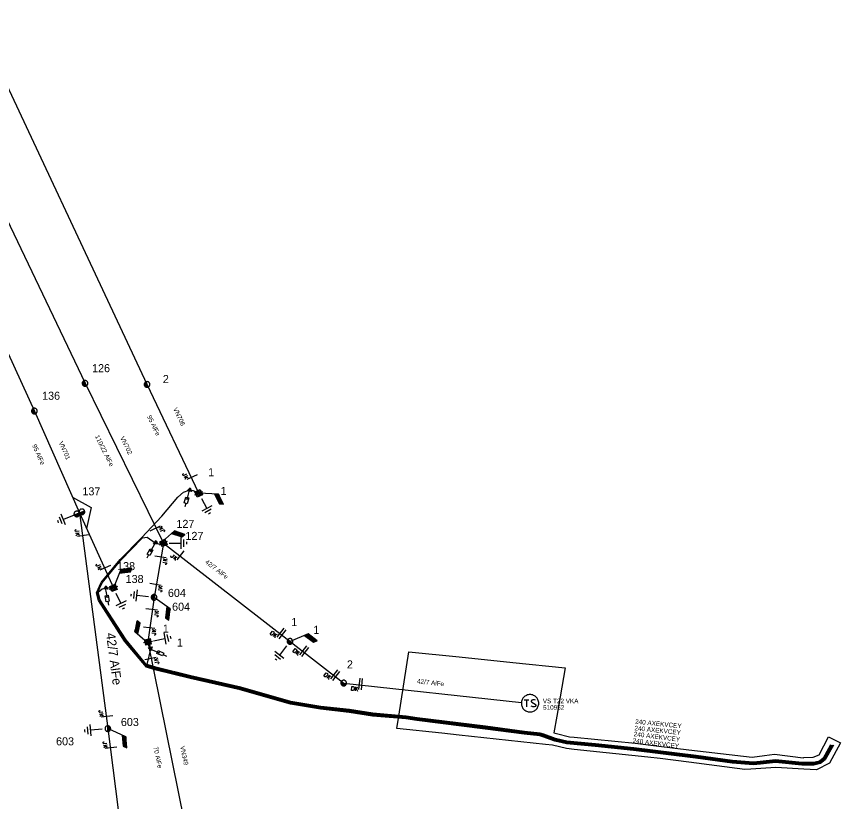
# Model space of a CAD drawing. Extents: x -536397 to -535454, y -1201642 to -1200953.
# Drawn here: x -536258.8 to -536079.5, y -1201331.1 to -1201160.3 of the extents above; entities that cross this region are included whole.
import ezdxf

# ---------------------------------------------------------------- set-up
doc = ezdxf.new("R2010")
doc.units = 0
for name, color, linetype in [('Default', 7, 'Continuous'), ('Vrstva 1', 7, 'Continuous'), ('Vrstva 11', 7, 'Continuous'), ('Vrstva 12', 7, 'Continuous'), ('Vrstva 13', 7, 'Continuous'), ('Vrstva 14', 7, 'Continuous'), ('Vrstva 15', 7, 'Continuous'), ('Vrstva 16', 7, 'Continuous'), ('Vrstva 18', 7, 'Continuous'), ('Vrstva 19', 7, 'Continuous'), ('Vrstva 2', 7, 'Continuous'), ('Vrstva 25', 7, 'Continuous'), ('Vrstva 26', 7, 'Continuous'), ('Vrstva 27', 7, 'Continuous'), ('Vrstva 3', 7, 'Continuous'), ('Vrstva 35', 7, 'Continuous'), ('Vrstva 4', 7, 'Continuous'), ('Vrstva 5', 7, 'Continuous'), ('Vrstva 52', 7, 'Continuous'), ('Vrstva 53', 7, 'Continuous'), ('Vrstva 57', 7, 'Continuous'), ('Vrstva 6', 7, 'Continuous')]:
    doc.layers.add(name, color=color, linetype=linetype)

# ---------------------------------------------------------------- blocks, each defined once
blk = doc.blocks.new('VN850')
at = {"layer": 'Vrstva 15'}
for points in [[(-0.56, 1.43), (-0.56, -1.07)], [(-0.01, 1.43), (-0.01, -1.07)], [(-2.09, -0.54), (-1.78, -0.54)], [(-2.09, -1.41), (-2.09, -0.54)], [(-1.78, -1.41), (-2.09, -1.41)], [(-1.78, -0.54), (-1.66, -0.6)], [(-1.67, -1.35), (-1.78, -1.41)], [(-1.59, -1.2), (-1.67, -1.35)], [(-1.66, -0.6), (-1.59, -0.75)], [(-1.59, -0.75), (-1.55, -0.96)], [(-1.55, -0.96), (-1.59, -1.2)], [(-1.26, -0.54), (-1.26, -1.41)], [(-0.85, -0.54), (-1.26, -1.09)], [(-1.13, -0.92), (-0.77, -1.41)]]:
    blk.add_lwpolyline(points, dxfattribs=at)
blk = doc.blocks.new('VN840')
at = {"layer": 'Vrstva 15'}
for points in [[(-0.01, 1.41), (-0.01, -1.09)], [(-1.51, -1.24), (-1.51, -1.15)], [(-1.48, -1.35), (-1.51, -1.24)], [(-1.33, -1.42), (-1.48, -1.35)], [(-1.27, -1.42), (-1.33, -1.42)], [(-1.13, -1.35), (-1.27, -1.42)], [(-1.09, -1.24), (-1.13, -1.35)], [(-1.09, -0.59), (-1.09, -1.24)], [(-0.68, -0.59), (-0.68, -1.42)], [(-0.68, -1.11), (-0.27, -0.59)], [(-0.54, -0.94), (-0.2, -1.42)]]:
    blk.add_lwpolyline(points, dxfattribs=at)
blk = doc.blocks.new('VN860')
at = {"layer": 'Vrstva 15'}
for points in [[(-3.74, 0), (0.01, 2.82)], [(0.01, 2.82), (3.76, 0)]]:
    blk.add_lwpolyline(points, dxfattribs=at)
blk = doc.blocks.new('VN440')
at = {"layer": 'Vrstva 2'}
for points in [[(1.22, 0), (1.21, 0.13), (1.19, 0.25), (1.16, 0.38), (1.11, 0.5), (1.05, 0.61), (0.98, 0.72), (0.9, 0.82), (0.81, 0.91), (0.71, 0.99), (0.6, 1.06), (0.49, 1.12), (0.37, 1.16), (0.25, 1.2), (0.12, 1.22), (-0.01, 1.22), (-0.14, 1.22), (-0.26, 1.2), (-0.39, 1.16), (-0.51, 1.12), (-0.62, 1.06), (-0.73, 0.99), (-0.83, 0.91), (-0.92, 0.82), (-1, 0.72), (-1.07, 0.61), (-1.13, 0.5), (-1.18, 0.38), (-1.21, 0.25), (-1.23, 0.13), (-1.24, 0), (-1.23, -0.13), (-1.21, -0.26), (-1.18, -0.38), (-1.13, -0.5), (-1.07, -0.62), (-1, -0.73), (-0.92, -0.83), (-0.83, -0.92), (-0.73, -1), (-0.62, -1.07), (-0.51, -1.13), (-0.39, -1.17), (-0.26, -1.2), (-0.14, -1.23), (-0.01, -1.23), (0.12, -1.23), (0.25, -1.2), (0.37, -1.17), (0.49, -1.13), (0.6, -1.07), (0.71, -1), (0.81, -0.92), (0.9, -0.83), (0.98, -0.73), (1.05, -0.62), (1.11, -0.5), (1.16, -0.38), (1.19, -0.26), (1.21, -0.13), (1.22, 0)], [(-1.24, 0), (1.22, 0)], [(-1.18, -0.34), (1.1, -0.34)], [(-1.01, -0.63), (0.97, -0.63)], [(-0.74, -0.92), (0.68, -0.92)]]:
    blk.add_lwpolyline(points, dxfattribs=at)
blk = doc.blocks.new('VN890')
at = {"layer": 'Vrstva 4'}
for points in [[(-0.41, 0.41), (0.41, 0)], [(-0.41, -0.41), (-0.41, 0.41)], [(0.41, 0), (-0.41, -0.41)], [(-0.34, 0.31), (0.27, 0), (-0.34, -0.3), (-0.34, 0.31)], [(-0.26, 0.2), (0.1, 0), (-0.26, -0.18), (-0.26, 0.2)], [(-0.19, 0.09), (-0.04, 0), (-0.19, -0.08), (-0.19, 0.09)], [(-0.16, -0.01), (-0.16, 0.03), (-0.13, 0.01), (-0.16, -0.01)]]:
    blk.add_lwpolyline(points, dxfattribs=at)
blk = doc.blocks.new('VN820')
at = {"layer": 'Vrstva 13'}
for points in [[(0, 0), (0, -2.1)], [(-0.32, -1.63), (0.34, -1.63)], [(-0.32, -2.95), (-0.32, -1.63)], [(0.34, -1.63), (0.34, -2.95)], [(0.34, -2.95), (-0.32, -2.95)], [(0, -2.1), (-0.12, -1.86)], [(0, -2.1), (0.12, -1.86)], [(0, -2.95), (0, -3.75)]]:
    blk.add_lwpolyline(points, dxfattribs=at)
blk = doc.blocks.new('VN810')
at = {"layer": 'Vrstva 14'}
for points in [[(0, -1.25), (0, -3.75)], [(1.25, -3.75), (-1.25, -3.75)], [(0.77, -4.37), (-0.8, -4.37)], [(0, -5), (-0.25, -5)], [(0.27, -5), (0, -5)]]:
    blk.add_lwpolyline(points, dxfattribs=at)
blk = doc.blocks.new('VN610')
at = {"layer": 'Vrstva 6'}
for points in [[(1.88, 0), (1.87, 0.2), (1.84, 0.39), (1.79, 0.58), (1.72, 0.77), (1.63, 0.94), (1.52, 1.11), (1.4, 1.26), (1.26, 1.4), (1.1, 1.53), (0.94, 1.63), (0.76, 1.72), (0.58, 1.8), (0.39, 1.85), (0.19, 1.88), (-0.01, 1.89), (-0.21, 1.88), (-0.4, 1.85), (-0.59, 1.8), (-0.78, 1.72), (-0.95, 1.63), (-1.12, 1.53), (-1.27, 1.4), (-1.41, 1.26), (-1.54, 1.11), (-1.64, 0.94), (-1.73, 0.77), (-1.8, 0.58), (-1.86, 0.39), (-1.89, 0.2), (-1.9, 0), (-1.89, -0.2), (-1.86, -0.39), (-1.8, -0.58), (-1.73, -0.77), (-1.64, -0.95), (-1.54, -1.11), (-1.41, -1.27), (-1.27, -1.41), (-1.12, -1.53), (-0.95, -1.64), (-0.78, -1.73), (-0.59, -1.8), (-0.4, -1.85), (-0.21, -1.88), (-0.01, -1.89), (0.19, -1.88), (0.39, -1.85), (0.58, -1.8), (0.76, -1.73), (0.94, -1.64), (1.1, -1.53), (1.26, -1.41), (1.4, -1.27), (1.52, -1.11), (1.63, -0.95), (1.72, -0.77), (1.79, -0.58), (1.84, -0.39), (1.87, -0.2), (1.88, 0)], [(-1.27, 0.78), (-0.26, 0.78)], [(-0.76, 0.78), (-0.76, -0.79)], [(1.19, 0.66), (0.94, 0.78), (0.62, 0.78), (0.37, 0.66), (0.24, 0.47), (0.24, 0.4), (0.37, 0.22), (1.12, -0.16), (1.25, -0.32), (1.25, -0.48), (1.12, -0.67), (0.87, -0.79), (0.62, -0.79), (0.49, -0.73), (0.24, -0.6)]]:
    blk.add_lwpolyline(points, dxfattribs=at)
blk = doc.blocks.new('VN450')
at = {"layer": 'Vrstva 2'}
for points in [[(0, 0), (-0.01, 0.13), (-0.03, 0.25), (-0.06, 0.38), (-0.11, 0.5), (-0.16, 0.61), (-0.23, 0.72), (-0.31, 0.82), (-0.4, 0.91), (-0.5, 0.99), (-0.61, 1.06), (-0.72, 1.11), (-0.84, 1.16), (-0.97, 1.19), (-1.09, 1.21), (-1.22, 1.22), (-1.35, 1.21), (-1.47, 1.19), (-1.59, 1.16), (-1.71, 1.11), (-1.83, 1.06), (-1.93, 0.99), (-2.03, 0.91), (-2.12, 0.82), (-2.2, 0.72), (-2.27, 0.61), (-2.33, 0.5), (-2.38, 0.38), (-2.41, 0.25), (-2.43, 0.13), (-2.44, 0), (-2.43, -0.13), (-2.41, -0.25), (-2.38, -0.38), (-2.33, -0.5), (-2.27, -0.61), (-2.2, -0.72), (-2.12, -0.82), (-2.03, -0.91), (-1.93, -0.99), (-1.83, -1.06), (-1.71, -1.11), (-1.59, -1.16), (-1.47, -1.19), (-1.35, -1.21), (-1.22, -1.22), (-1.09, -1.21), (-0.97, -1.19), (-0.84, -1.16), (-0.72, -1.11), (-0.61, -1.06), (-0.5, -0.99), (-0.4, -0.91), (-0.31, -0.82), (-0.23, -0.72), (-0.16, -0.61), (-0.11, -0.5), (-0.06, -0.38), (-0.03, -0.25), (-0.01, -0.13), (0, 0)], [(-2.44, 0), (2.44, 0)], [(2.44, 0), (2.43, 0.13), (2.41, 0.25), (2.38, 0.38), (2.33, 0.5), (2.27, 0.61), (2.2, 0.72), (2.12, 0.82), (2.03, 0.91), (1.94, 0.99), (1.83, 1.06), (1.71, 1.11), (1.6, 1.16), (1.47, 1.19), (1.35, 1.21), (1.22, 1.22), (1.09, 1.21), (0.97, 1.19), (0.84, 1.16), (0.72, 1.11), (0.61, 1.06), (0.5, 0.99), (0.4, 0.91), (0.31, 0.82), (0.23, 0.72), (0.16, 0.61), (0.11, 0.5), (0.06, 0.38), (0.03, 0.25), (0.01, 0.13), (0, 0), (0.01, -0.13), (0.03, -0.25), (0.06, -0.38), (0.11, -0.5), (0.16, -0.61), (0.23, -0.72), (0.31, -0.82), (0.4, -0.91), (0.5, -0.99), (0.61, -1.06), (0.72, -1.11), (0.84, -1.16), (0.97, -1.19), (1.09, -1.21), (1.22, -1.22), (1.35, -1.21), (1.47, -1.19), (1.6, -1.16), (1.71, -1.11), (1.83, -1.06), (1.94, -0.99), (2.03, -0.91), (2.12, -0.82), (2.2, -0.72), (2.27, -0.61), (2.33, -0.5), (2.38, -0.38), (2.41, -0.25), (2.43, -0.13), (2.44, 0)], [(-2.4, -0.31), (-0.04, -0.31)], [(-2.26, -0.61), (-0.17, -0.61)], [(-2.01, -0.92), (-0.42, -0.92)], [(0.04, -0.31), (2.4, -0.31)], [(0.17, -0.61), (2.27, -0.61)], [(0.42, -0.92), (2.02, -0.92)]]:
    blk.add_lwpolyline(points, dxfattribs=at)
blk = doc.blocks.new('VN001')
at = {"layer": 'Default'}
for p, q in [((2.07, 3.63), (4.49, 3.63)), ((2.1, 3.68), (4.52, 3.68)), ((2.13, 3.73), (2.54, 3.73)), ((1.73, 3.03), (4.14, 3.03)), ((1.76, 3.08), (4.17, 3.08)), ((1.79, 3.13), (4.2, 3.13)), ((1.82, 3.18), (4.23, 3.18)), ((1.85, 3.23), (4.26, 3.23)), ((1.87, 3.28), (4.29, 3.28)), ((1.9, 3.33), (4.32, 3.33)), ((1.93, 3.38), (4.35, 3.38)), ((1.96, 3.43), (4.37, 3.43)), ((1.99, 3.48), (4.4, 3.48)), ((2.02, 3.53), (4.43, 3.53)), ((2.05, 3.58), (4.46, 3.58))]:
    blk.add_line(p, q, dxfattribs=at)
blk.add_lwpolyline([(2.13, 3.73), (0, 0)], dxfattribs=at)
blk.add_lwpolyline([(4.55, 3.73), (2.13, 3.73), (1.7, 2.98), (4.12, 2.99)], close=True, dxfattribs=at)
blk = doc.blocks.new('VN470')
at = {"layer": 'Vrstva 2'}
for points in [[(-1.23, 1.22), (1.23, 1.22)], [(-1.23, -1.23), (-1.23, 1.22)], [(-0.92, 0.9), (0.92, 0.9)], [(-0.92, -0.95), (-0.92, 0.9)], [(-0.61, 0.61), (0.61, 0.61)], [(-0.61, -0.62), (-0.61, 0.61)], [(-0.31, -0.27), (-0.31, 0.34)], [(-0.31, 0.34), (0.31, 0.34)], [(0, 1.22), (0, 1.97)], [(0.31, 0.34), (0.31, -0.27)], [(0.61, 0.61), (0.61, -0.62)], [(0.92, 0.9), (0.92, -0.95)], [(1.23, 1.22), (1.23, -1.23)], [(1.23, -1.23), (-1.23, -1.23)], [(0.92, -0.95), (-0.92, -0.95)], [(0.61, -0.62), (-0.61, -0.62)], [(0.31, -0.27), (-0.31, -0.27)], [(0, -1.23), (0, -1.98)]]:
    blk.add_lwpolyline(points, dxfattribs=at)

msp = doc.modelspace()

# ---------------------------------------------------------------- linework, layer by layer
at = {"layer": 'Vrstva 1'}
for points in [[(-536219.16, -1201264.03), (-536230.39, -1201240.36), (-536267.93, -1201160.31)], [(-536279.58, -1201165.38), (-536243.88, -1201240.11), (-536226.82, -1201274.86)], [(-536289.66, -1201170.08), (-536254.89, -1201246.15), (-536245.11, -1201268.29)], [(-536245.11, -1201268.29), (-536237.69, -1201284.62)], [(-536230.2, -1201296.37), (-536218.34, -1201355.12), (-536212.54, -1201404.88), (-536207.27, -1201451.49)]]:
    msp.add_lwpolyline(points, dxfattribs=at)
at = {"layer": 'Vrstva 35'}
msp.add_lwpolyline([(-536138.46, -1201317.01), (-536137.5, -1201317.1), (-536124.22, -1201318.41), (-536119.04, -1201319.04), (-536112.5, -1201319.83), (-536110.67, -1201320.05), (-536098.79, -1201321.42), (-536096.07, -1201321.07), (-536093.87, -1201320.79), (-536087.69, -1201321.55), (-536087.5, -1201321.54), (-536085.51, -1201321.45), (-536084.19, -1201320.96), (-536082.15, -1201317.03), (-536079.54, -1201318.31), (-536081.95, -1201322.74), (-536084.75, -1201324.2), (-536087.5, -1201324.04), (-536093.62, -1201323.7), (-536099.05, -1201324.05), (-536100.32, -1201324.13), (-536112.5, -1201322.53), (-536118.8, -1201321.71), (-536121.43, -1201321.43), (-536137.5, -1201319.75), (-536139.14, -1201319.58), (-536142.2, -1201318.86), (-536143.7, -1201318.7), (-536162.5, -1201316.65), (-536166.25, -1201316.25), (-536176.07, -1201315.18), (-536175.65, -1201312.5), (-536173.46, -1201298.49), (-536162.5, -1201299.62), (-536150.83, -1201300.83), (-536139.43, -1201302.01), (-536141.28, -1201312.5), (-536141.93, -1201316.15), (-536141.3, -1201316.3)], close=True, dxfattribs=at)
at = {"layer": 'Vrstva 4'}
for points in [[(-536226.82, -1201274.86), (-536199.29, -1201296.25)], [(-536199.29, -1201296.25), (-536187.61, -1201305.32), (-536148.9, -1201309.51)]]:
    msp.add_lwpolyline(points, dxfattribs=at)
at = {"layer": 'Vrstva 5'}
for points in [[(-536081.04, -1201318.84), (-536082.85, -1201322.02), (-536083.86, -1201322.84), (-536085.34, -1201323.19), (-536087.93, -1201323.18), (-536093.65, -1201322.62), (-536096.93, -1201322.98), (-536098.44, -1201323.12), (-536103.13, -1201322.77), (-536111.05, -1201321.64), (-536124.55, -1201319.99), (-536132.93, -1201319.15), (-536139.13, -1201318.52), (-536141.67, -1201317.98), (-536144.29, -1201317.03), (-536144.98, -1201316.82), (-536148.36, -1201316.45), (-536156.86, -1201315.32), (-536171.69, -1201313.45), (-536174.08, -1201313.11), (-536181.38, -1201312.49), (-536186.41, -1201311.69), (-536192.65, -1201311.01), (-536199.22, -1201309.92), (-536210.16, -1201306.78), (-536221.01, -1201304.32), (-536228.67, -1201302.47), (-536230.49, -1201301.88), (-536235.26, -1201296.17), (-536240.98, -1201287.39), (-536241.39, -1201285.72), (-536240.35, -1201283.41), (-536236.24, -1201278.45), (-536231.61, -1201273.69), (-536227.17, -1201268.98), (-536223.69, -1201264.85), (-536222.46, -1201263.79), (-536221.26, -1201263.36), (-536220.36, -1201263.43), (-536219.16, -1201264.03)], [(-536081.26, -1201318.81), (-536083.01, -1201321.89), (-536083.95, -1201322.65), (-536085.37, -1201322.99), (-536087.92, -1201322.98), (-536093.65, -1201322.42), (-536096.95, -1201322.78), (-536098.44, -1201322.92), (-536103.11, -1201322.57), (-536111.03, -1201321.44), (-536124.53, -1201319.79), (-536132.91, -1201318.95), (-536139.1, -1201318.32), (-536141.61, -1201317.78), (-536144.22, -1201316.84), (-536144.94, -1201316.63), (-536148.34, -1201316.25), (-536156.83, -1201315.12), (-536171.66, -1201313.25), (-536174.06, -1201312.91), (-536181.35, -1201312.29), (-536186.38, -1201311.49), (-536192.62, -1201310.81), (-536199.17, -1201309.73), (-536210.1, -1201306.59), (-536220.96, -1201304.13), (-536228.62, -1201302.28), (-536230.43, -1201301.69), (-536235.1, -1201296.05), (-536240.79, -1201287.31), (-536241.2, -1201285.67), (-536240.17, -1201283.51), (-536236.1, -1201278.59), (-536231.47, -1201273.83), (-536231.37, -1201273.73), (-536230.35, -1201273.57), (-536228.63, -1201274.83), (-536227.65, -1201275.07)], [(-536081.48, -1201318.79), (-536083.16, -1201321.76), (-536084.04, -1201322.47), (-536085.39, -1201322.79), (-536087.91, -1201322.78), (-536093.65, -1201322.22), (-536096.97, -1201322.58), (-536098.44, -1201322.72), (-536103.09, -1201322.37), (-536111, -1201321.24), (-536124.51, -1201319.59), (-536132.89, -1201318.75), (-536139.07, -1201318.12), (-536141.56, -1201317.59), (-536144.16, -1201316.65), (-536144.9, -1201316.43), (-536148.32, -1201316.05), (-536156.81, -1201314.92), (-536171.64, -1201313.05), (-536174.04, -1201312.71), (-536181.33, -1201312.09), (-536186.36, -1201311.29), (-536192.6, -1201310.61), (-536199.13, -1201309.53), (-536210.06, -1201306.39), (-536220.92, -1201303.93), (-536228.56, -1201302.08), (-536230.37, -1201301.5), (-536234.94, -1201295.93), (-536240.6, -1201287.23), (-536241.03, -1201285.53), (-536240.15, -1201284.85), (-536239.48, -1201284.67), (-536238.55, -1201284.55), (-536237.69, -1201284.62)], [(-536081.69, -1201318.77), (-536083.31, -1201321.63), (-536084.13, -1201322.29), (-536085.41, -1201322.59), (-536087.9, -1201322.58), (-536093.65, -1201322.02), (-536096.99, -1201322.38), (-536098.44, -1201322.52), (-536103.07, -1201322.17), (-536110.97, -1201321.04), (-536124.49, -1201319.39), (-536132.87, -1201318.55), (-536139.04, -1201317.92), (-536141.51, -1201317.4), (-536144.1, -1201316.46), (-536144.86, -1201316.23), (-536148.3, -1201315.85), (-536156.78, -1201314.72), (-536171.61, -1201312.85), (-536174.02, -1201312.51), (-536181.3, -1201311.89), (-536186.33, -1201311.09), (-536192.57, -1201310.41), (-536199.08, -1201309.34), (-536210.01, -1201306.2), (-536220.87, -1201303.74), (-536228.51, -1201301.89), (-536230.34, -1201301.29), (-536229.6, -1201297.92), (-536229.77, -1201296.93)]]:
    msp.add_lwpolyline(points, dxfattribs=at)
at = {"layer": 'Vrstva 52'}
for points in [[(-536245.11, -1201268.29), (-536238.92, -1201315.23)], [(-536226.82, -1201274.86), (-536228.86, -1201286.67)], [(-536228.86, -1201286.67), (-536230.2, -1201296.37)], [(-536238.92, -1201315.23), (-536232.79, -1201363.72), (-536227.13, -1201407.48), (-536207.27, -1201451.49)]]:
    msp.add_lwpolyline(points, dxfattribs=at)

# ---------------------------------------------------------------- block references
at = {"layer": 'Vrstva 11'}
for p, rotation in [((-536219.16, -1201264.03), -63.04782218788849), ((-536227.65, -1201275.07), -18.412788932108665), ((-536237.69, -1201284.62), 7.734305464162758), ((-536228.86, -1201286.67), -96.34487777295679), ((-536229.77, -1201296.93), 78.9054638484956), ((-536199.29, -1201296.25), -37.845780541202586), ((-536238.92, -1201315.23), -84.65707223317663)]:
    msp.add_blockref('VN001', p, dxfattribs=dict(at, rotation=rotation))
at = {"layer": 'Vrstva 13'}
for name, p, xscale, yscale, rotation in [('VN440', (-536243.88, -1201240.11), 0.5, 0.49999999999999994, -64.4647500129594), ('VN440', (-536230.39, -1201240.36), 0.5, 0.5, -64.87521117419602), ('VN440', (-536254.89, -1201246.15), 0.5, 0.5, -65.43590001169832), ('VN470', (-536219.16, -1201264.03), 0.49999999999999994, 0.5000000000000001, -65.65072218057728), ('VN450', (-536245.11, -1201268.29), 0.49999999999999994, 0.5000000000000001, 22.397824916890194), ('VN470', (-536226.82, -1201274.86), 0.5000000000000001, 0.5, 116.01055560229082), ('VN470', (-536237.69, -1201284.62), 0.5, 0.5, -67.60211944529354), ('VN440', (-536228.86, -1201286.67), 0.5000000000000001, 0.5, -96.35033613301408), ('VN470', (-536230.2, -1201296.37), 0.5, 0.5, 101.19134719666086), ('VN440', (-536199.29, -1201296.25), 0.49999999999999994, 0.5000000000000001, -37.8457360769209), ('VN440', (-536187.61, -1201305.32), 0.5, 0.5, -37.83150002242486), ('VN440', (-536238.92, -1201315.23), 0.5, 0.5000000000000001, 86.69934168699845)]:
    msp.add_blockref(name, p, dxfattribs=dict(at, xscale=xscale, yscale=yscale, rotation=rotation))
at = {"layer": 'Vrstva 15'}
for p, rotation in [((-536219.16, -1201264.03), 28.219202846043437), ((-536245.11, -1201268.29), -67.60749723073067), ((-536226.82, -1201274.86), 89.79945003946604), ((-536237.69, -1201284.62), 25.76595266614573), ((-536228.86, -1201286.67), -96.34631667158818), ((-536230.2, -1201296.37), 101.36385831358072), ((-536199.29, -1201296.25), -37.84640564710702), ((-536238.92, -1201315.23), -84.65707223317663)]:
    msp.add_blockref('VN810', p, dxfattribs=dict(at, rotation=rotation))
at = {"layer": 'Vrstva 16'}
for p, rotation in [((-536221.26, -1201263.36), -13.990508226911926), ((-536228.63, -1201274.83), -28.8901470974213), ((-536239.48, -1201284.67), 10.619655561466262), ((-536229.61, -1201297.92), 66.19975004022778)]:
    msp.add_blockref('VN820', p, dxfattribs=dict(at, rotation=rotation))
at = {"layer": 'Vrstva 18'}
for name, p, rotation in [('VN840', (-536220.78, -1201260.61), -64.61845551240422), ('VN860', (-536245.11, -1201268.29), -66.11288332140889), ('VN840', (-536228.44, -1201271.57), 116.1480499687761), ('VN840', (-536244.45, -1201273.27), -82.48772505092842), ('VN840', (-536223.24, -1201277.64), -37.84615556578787), ('VN840', (-536227.33, -1201277.84), 80.1997222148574), ('VN840', (-536239.63, -1201280.35), -65.56397498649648), ('VN840', (-536228.36, -1201283.8), 80.1997222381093), ('VN840', (-536229.22, -1201289.26), 82.13469442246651), ('VN850', (-536201.09, -1201294.85), -37.84615554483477), ('VN840', (-536229.77, -1201293.24), 82.13469442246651), ('VN850', (-536196.16, -1201298.68), -37.83080836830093), ('VN840', (-536229.49, -1201299.89), 101.4130471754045), ('VN850', (-536189.41, -1201303.92), -37.83080836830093), ('VN850', (-536183.71, -1201305.74), -6.180297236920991), ('VN840', (-536239.26, -1201312.62), -82.48772501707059), ('VN840', (-536238.39, -1201319.44), -82.79501113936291)]:
    msp.add_blockref(name, p, dxfattribs=dict(at, rotation=rotation))
at = {"layer": 'Vrstva 19'}
for p, rotation in [((-536221.26, -1201263.36), -160.28570550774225), ((-536228.63, -1201274.83), -154.34267780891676), ((-536239.48, -1201284.67), -158.4331499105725), ((-536229.61, -1201297.92), -78.9704277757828)]:
    msp.add_blockref('VN890', p, dxfattribs=dict(at, rotation=rotation))
at = {"layer": 'Vrstva 25', "rotation": 0.005252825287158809}
msp.add_blockref('VN610', (-536147.07, -1201309.71), dxfattribs=at)

# ---------------------------------------------------------------- texts
at = {"layer": 'Vrstva 12'}
for s, p in [('1', (-536214.4, -1201264.4)), ('127', (-536222.04, -1201274.18)), ('138', (-536236.9, -1201280.75)), ('604', (-536224.94, -1201289.58)), ('1', (-536226.96, -1201294.34)), ('1', (-536194.21, -1201294.61)), ('603', (-536250.18, -1201318.86))]:
    msp.add_text(s, height=1.75, dxfattribs=at).set_placement(p)
at = {"layer": 'Vrstva 14'}
for s, p in [('126', (-536242.35, -1201237.69)), ('2', (-536226.95, -1201240.05)), ('136', (-536253.22, -1201243.69)), ('1', (-536217.1, -1201260.32)), ('137', (-536244.45, -1201264.48)), ('127', (-536224, -1201271.56)), ('138', (-536235.05, -1201283.55)), ('604', (-536225.85, -1201286.58)), ('1', (-536199.03, -1201292.93)), ('1', (-536223.89, -1201297.38)), ('2', (-536186.91, -1201302.13)), ('603', (-536236.08, -1201314.66))]:
    msp.add_text(s, height=1.75, dxfattribs=at).set_placement(p)
at = {"layer": 'Vrstva 2'}
for s, rotation, p in [('95 AlFe', 295.382, (-536230.41, -1201247.34)), ('110/22 AlFe', 296.148, (-536241.75, -1201251.65)), ('95 AlFe', 293.833, (-536255.4, -1201253.63)), ('70 AlFe', 281.413, (-536228.99, -1201319.26))]:
    msp.add_text(s, height=1, rotation=rotation, dxfattribs=at).set_placement(p)
at = {"layer": 'Vrstva 26'}
msp.add_text('510952', height=1, dxfattribs=at).set_placement((-536144.24, -1201311.12))
at = {"layer": 'Vrstva 27'}
msp.add_text('VS T22 VKA', height=1, dxfattribs=at).set_placement((-536144.3, -1201309.71))
at = {"layer": 'Vrstva 3'}
for s, rotation, p in [('VN706', 295.382, (-536224.75, -1201245.66)), ('VN701', 293.833, (-536249.63, -1201253)), ('VN702', 296.148, (-536236.29, -1201251.96)), ('VN349', 281.413, (-536223.18, -1201319.11))]:
    msp.add_text(s, height=1, rotation=rotation, dxfattribs=at).set_placement(p)
at = {"layer": 'Vrstva 53'}
msp.add_text('42/7 AlFe', height=2, rotation=277.512, dxfattribs=at).set_placement((-536239.32, -1201294.51))
at = {"layer": 'Vrstva 57'}
for rotation, p in [(322.154, (-536217.87, -1201279.15)), (353.82, (-536171.71, -1201305.38))]:
    msp.add_text('42/7 AlFe', height=1, rotation=rotation, dxfattribs=at).set_placement(p)
at = {"layer": 'Vrstva 6'}
for rotation, p in [(354.277, (-536124.25, -1201314.15)), (354.276, (-536124.4, -1201315.58)), (353.036, (-536124.79, -1201318.29)), (353.039, (-536124.55, -1201316.86))]:
    msp.add_text('240 AXEKVCEY', height=1, rotation=rotation, dxfattribs=at).set_placement(p)

doc.saveas('drawing.dxf')
